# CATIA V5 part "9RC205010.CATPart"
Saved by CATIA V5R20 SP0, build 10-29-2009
Part number: 9RC205010
Revision: ANY
Definition: UNKNOWN
Nomenclature: 9RC205010
Source: Unknown
Bounding box of the stored display mesh (mm): x -39.23 to 10, y -10 to 10, z -3.85 to 3.85
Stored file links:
  C:\Users\Utente\Desktop\IO LAVORO\3D X SITO CF\CUMSA\3D files RC\RC 205010\9RC205010.CATPart
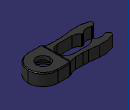
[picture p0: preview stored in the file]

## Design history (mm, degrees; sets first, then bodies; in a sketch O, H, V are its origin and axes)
Body1 "Chaflán1" (main body)
  Solid1: solid without history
